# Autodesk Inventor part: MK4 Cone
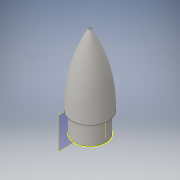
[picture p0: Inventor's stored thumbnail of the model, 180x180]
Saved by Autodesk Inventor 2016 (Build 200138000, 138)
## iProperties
Created: 2015-09
Part Number: MK4 Cone
Material: Generic
Document SubType Name: Modeling
Designer: lwilliams6899
Density: 1 g/cm^3
Appearance: Default
Author: lwilliams6899
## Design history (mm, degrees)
sketch "Sketch1"
  geometry: C1 r 11.049 at (0, 0); 1 further point
  constraints: 1 centre point, 1 coincident
  dimensions: "d0" = 22.098 diameter of C1
extrude "Extrusion1" new body sketch "Sketch1" distance "d1" = 13.97; taper "d2" = 0 deg
sketch "Sketch2"
  geometry: L1 (0, 0)-(-2.841, 0); L2 (0, 0)-(0, -2.273)
  constraints: 4 end point, 1 horizontal, 1 vertical
workplane "Work Plane1"
sketch "Sketch3"
  geometry: L1 (11.049, 0)-(-11.049, 0) reference; L2 (-11.049, -13.97)-(11.049, -13.97) reference; L3 (11.049, 0)-(-11.049, 0) reference; L4 (11.049, 0)-(-11.049, 0) reference; L5 (0, 0)-(-12.7, 0); L6 (0, 0)-(0, 50.8); A1 r 94.865 centre (82.108, 3.285) between (-1.002, 49.024) and (-12.7, 0); A2 r 1.569 centre (0, 47.929) between (0, 49.498) and (-0.624, 49.368); A3 r 0.791 centre (-0.31, 48.643) between (-0.624, 49.368) and (-1.002, 49.024); 1 further point
  constraints: 6 point on circle, 4 end point, 3 centre point, 3 point on line, 2 tangent, 1 midpoint, 1 perpendicular
  dimensions: "d3" = 12.7 distance of L5.start L5.end; "d4" = 50.8 distance of L5.start L6.end
revolve "Revolution1" sketch "Sketch3" stored, may be unused: angle "d5" = 90 deg
sketch "Sketch4"
  geometry: L1 (0, 0)-(-9.525, 0); L2 (-9.525, 0)-(-9.525, -2.54); L3 (-9.525, -2.54)-(-6.985, -2.54); L4 (-6.985, -2.54)-(-6.985, 2.54); L5 (-6.985, 2.54)-(-9.525, 2.54); L6 (-9.525, 2.54)-(-9.525, 0)
  constraints: 12 end point, 3 perpendicular, 1 collinear, 1 horizontal, 1 point on line, 1 vertical
  dimensions: "d6" = 9.525 distance of L1.start L1.end; "d7" = 2.54 distance of L1.end L2.end; "d8" = 2.54 distance of L2.end L3.end; "d9" = 5.08 distance of L3.end L4.end
extrude "Extrusion2" cut sketch "Sketch4" distance "d10" = 5.08; taper "d11" = 0 deg
sketch "Sketch5"
  geometry: L1 (-6.985, -2.54)-(-9.525, -2.54) reference; L2 (-9.525, -2.54)-(-9.525, 2.54) reference; L3 (-9.525, 2.54)-(-6.985, 2.54) reference; L4 (-6.985, 2.54)-(-6.985, -2.54) reference; L5 (-10.343, 0)-(-11.049, 0); L6 (-11.049, -2.215)-(-11.049, 0); 3 further points
  constraints: 4 end point, 1 perpendicular, 6 other
  node "Projected Loop3"
workplane "Work Plane2"
sketch "Sketch6"
  geometry: L1 (0, 2.54)-(0, -2.54) reference; L2 (0, 2.54)-(-5.08, 2.54) reference; L3 (-5.08, 2.54)-(-5.08, -2.54) reference; L4 (0, -2.54)-(-5.08, -2.54) reference; L5 (-5.08, -2.54)-(-5.08, 2.54) reference; L6 (-5.08, -2.54)-(-5.08, 2.54); L7 (-5.08, 2.54)-(-2.54, 2.54); L8 (0, 2.54)-(-5.08, 2.54) reference; L9 (-2.54, 2.54)-(-2.54, -2.54); L10 (0, -2.54)-(-5.08, -2.54) reference; L11 (-5.08, -2.54)-(-2.54, -2.54); 1 further point
  constraints: 8 end point, 2 collinear, 2 midpoint
  dimensions: "d12" = 2.54 distance of L2.end L7.end (derived)
extrude "Extrusion3" cut sketch "Sketch6" stored distance "d13" = 5.08; taper "d14" = 0 deg
sketch "Sketch7"
  geometry: L1 (-6.985, 2.54)-(-6.985, -2.54) reference; L2 (-9.525, 2.54)-(-6.985, 2.54) reference; L3 (-9.525, -2.54)-(-9.525, 2.54) reference; L4 (-6.985, -2.54)-(-9.525, -2.54) reference; L5 (-6.215, -2.54)-(-6.215, 2.54); 1 further point
  constraints: 2 end point, 1 vertical
revolve "Revolution2" sketch "Sketch7" stored, may be unused: angle "d15" = 90 deg
thicken "Thicken1" dims "d16" = 0.254, "d17" = 0.254
sketch "Sketch8"
  geometry: 2 further points
body "Solid1"
node "Projected Loop1"
node "Projected Loop2"
node "Projected Loop4"
